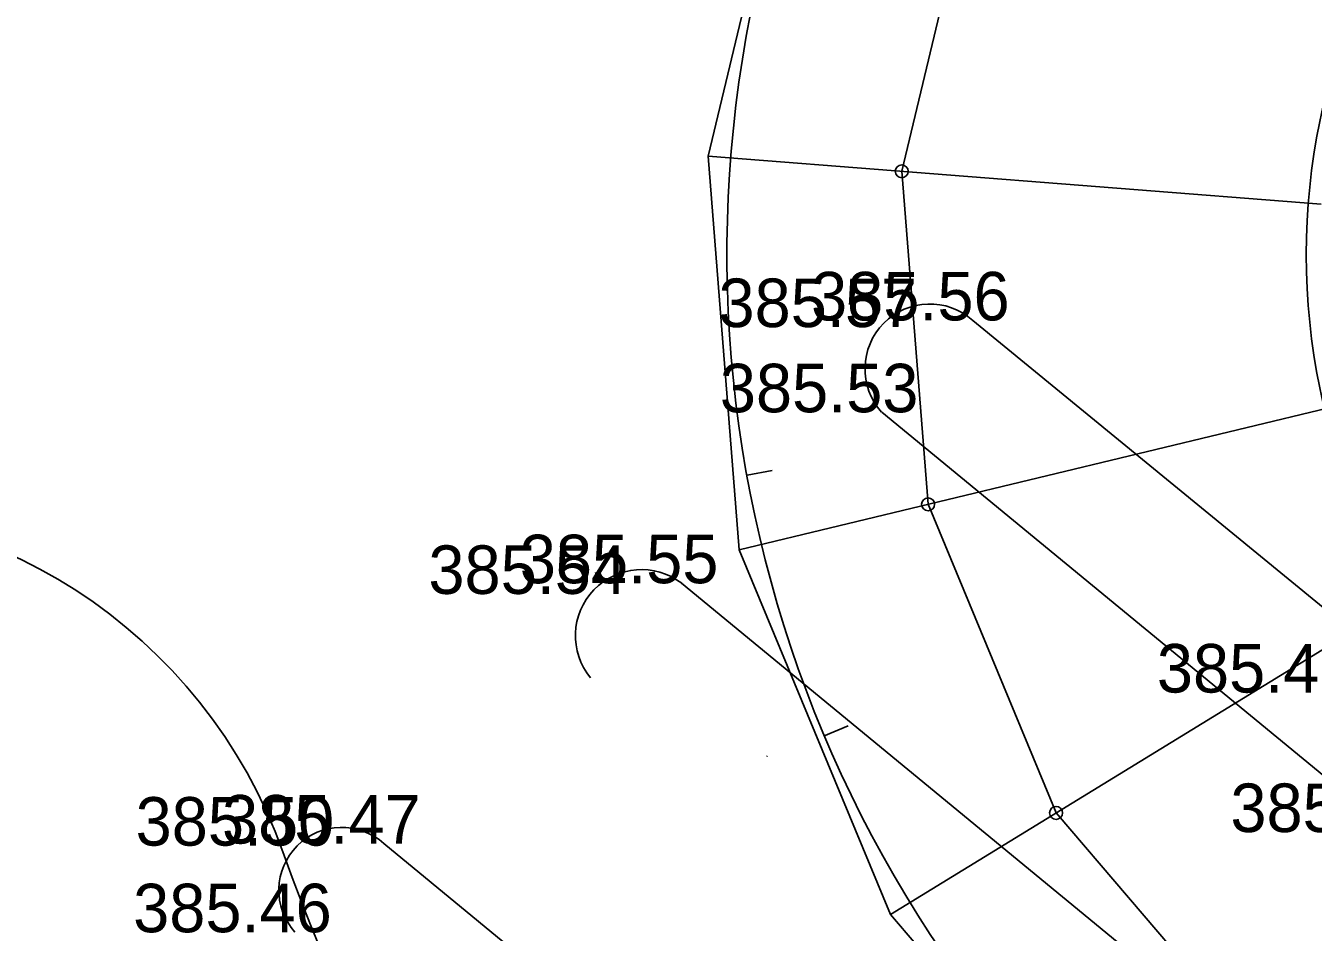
# Model space of a CAD drawing. Extents: x -438233 to -437334, y -1133133 to -1132623.
# Drawn here: x -438087.94 to -438068.05, y -1132962.38 to -1132948.37 of the extents above; entities that cross this region are included whole.
import ezdxf

# ---------------------------------------------------------------- set-up
doc = ezdxf.new("R2010")
doc.units = 0
for name, color, linetype in [('OSY', 7, 'Continuous'), ('SILNA 1', 7, 'Continuous'), ('Vrstva 1', 7, 'Continuous'), ('Vrstva 10', 7, 'Continuous'), ('Vrstva 15', 7, 'Continuous'), ('Vrstva 3', 7, 'Continuous'), ('Vrstva 50', 7, 'Continuous')]:
    doc.layers.add(name, color=color, linetype=linetype)

msp = doc.modelspace()

# ---------------------------------------------------------------- linework, layer by layer
at = {"layer": 'DEFPOINTS'}
msp.add_circle((-438057.962, -1132951.913), 10.2, dxfattribs=at)
at = {"layer": 'OSY'}
for p, q in [((-438067.931, -1132951.133), (-438077.402, -1132950.391)), ((-438067.685, -1132954.251), (-438076.921, -1132956.473)), ((-438074.584, -1132962.109), (-438066.486, -1132957.141))]:
    msp.add_line(p, q, dxfattribs=at)
for points in [[(-438050.507, -1132933.894), (-438056.44, -1132932.473), (-438062.522, -1132932.954), (-438068.157, -1132935.291), (-438072.795, -1132939.255), (-438075.98, -1132944.458), (-438077.402, -1132950.391), (-438076.921, -1132956.473), (-438074.584, -1132962.109), (-438070.62, -1132966.746), (-438065.417, -1132969.932), (-438059.484, -1132971.354), (-438053.402, -1132970.872), (-438047.766, -1132968.535), (-438043.129, -1132964.571), (-438039.943, -1132959.368), (-438038.521, -1132953.435), (-438039.002, -1132947.353), (-438041.339, -1132941.718), (-438045.304, -1132937.08)], [(-438056.674, -1132935.463), (-438061.82, -1132935.87), (-438066.589, -1132937.848), (-438070.513, -1132941.202), (-438073.208, -1132945.605), (-438074.411, -1132950.625), (-438074.004, -1132955.771), (-438072.027, -1132960.54), (-438068.673, -1132964.464), (-438064.27, -1132967.16), (-438059.25, -1132968.363), (-438054.103, -1132967.956), (-438049.335, -1132965.978), (-438045.411, -1132962.624), (-438042.715, -1132958.221), (-438041.512, -1132953.201), (-438041.919, -1132948.055), (-438043.897, -1132943.286), (-438047.251, -1132939.362), (-438051.654, -1132936.666)], [(-438056.674, -1132935.463), (-438061.82, -1132935.87), (-438066.589, -1132937.848), (-438070.513, -1132941.202), (-438073.208, -1132945.605), (-438074.411, -1132950.625), (-438074.004, -1132955.771), (-438072.027, -1132960.54), (-438068.673, -1132964.464), (-438064.27, -1132967.16), (-438059.25, -1132968.363), (-438054.103, -1132967.956), (-438049.335, -1132965.978), (-438045.411, -1132962.624), (-438042.715, -1132958.221), (-438041.512, -1132953.201), (-438041.919, -1132948.055), (-438043.897, -1132943.286), (-438047.251, -1132939.362), (-438051.654, -1132936.666)]]:
    msp.add_lwpolyline(points, close=True, dxfattribs=at)
at = {"layer": 'SILNA 1'}
for centre in [(-438074.411, -1132950.625), (-438074.411, -1132950.625), (-438074.004, -1132955.771), (-438074.004, -1132955.771), (-438072.027, -1132960.54), (-438072.027, -1132960.54)]:
    msp.add_circle(centre, 0.1, dxfattribs=at)
at = {"layer": 'Vrstva 1'}
for p, q in [((-438074.742, -1132953.032), (-438074.742, -1132953.032)), ((-438073.312, -1132952.929), (-438073.312, -1132952.929)), ((-438074.721, -1132954.349), (-438074.721, -1132954.349)), ((-438077.811, -1132956.991), (-438077.811, -1132956.991)), ((-438079.223, -1132957.156), (-438079.223, -1132957.156)), ((-438079.217, -1132958.451), (-438079.217, -1132958.451)), ((-438083.746, -1132961.046), (-438083.746, -1132961.046)), ((-438082.411, -1132961.014), (-438082.411, -1132961.014))]:
    msp.add_line(p, q, dxfattribs=at)
for centre, radius, start, end in [((-438057.961, -1132951.909), 19.15, 161.159, 229.4804), ((-438091.512, -1132963.819), 8, 19.5386, 94.7378), ((-438057.962, -1132951.913), 27.6, 199.5386, 254.3601)]:
    msp.add_arc(centre, radius, start, end, dxfattribs=at)
at = {"layer": 'Vrstva 10'}
for points in [[(-438073.312, -1132952.929), (-438056.933, -1132966.353)], [(-438074.721, -1132954.349), (-438058.129, -1132968.002)], [(-438077.811, -1132956.991), (-438061.441, -1132970.477)], [(-438082.411, -1132961.014), (-438066.062, -1132974.491)]]:
    msp.add_lwpolyline(points, dxfattribs=at)
for centre, radius, start, end in [((-438073.977, -1132953.678), 1.002, 48.429, 222.0165), ((-438078.432, -1132957.8), 1.02, 52.4791, 219.6798), ((-438083.062, -1132961.735), 0.971, 47.9569, 221.9595)]:
    msp.add_arc(centre, radius, start, end, dxfattribs=at)
at = {"layer": 'Vrstva 15'}
for p, q in [((-438076.799, -1132955.321), (-438076.411, -1132955.251)), ((-438075.618, -1132959.354), (-438075.238, -1132959.194))]:
    msp.add_line(p, q, dxfattribs=at)
at = {"layer": 'Vrstva 50'}
msp.add_line((-438076.497, -1132959.668), (-438076.489, -1132959.66), dxfattribs=at)

# ---------------------------------------------------------------- texts
at = {"layer": 'Vrstva 3'}
for s, p in [('385.57 ', (-438077.242, -1132953.032)), ('385.56 ', (-438075.812, -1132952.929)), ('385.53 ', (-438077.221, -1132954.349)), ('385.55 ', (-438080.311, -1132956.991)), ('385.54 ', (-438081.723, -1132957.156)), ('385.48 ', (-438070.47, -1132958.68)), ('385.47 ', (-438084.911, -1132961.014)), ('385.29 ', (-438069.334, -1132960.836)), ('385.50 ', (-438086.246, -1132961.046)), ('385.46 ', (-438086.284, -1132962.385))]:
    msp.add_text(s, height=0.75, dxfattribs=at).set_placement(p)

doc.saveas('drawing.dxf')
